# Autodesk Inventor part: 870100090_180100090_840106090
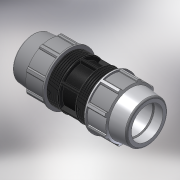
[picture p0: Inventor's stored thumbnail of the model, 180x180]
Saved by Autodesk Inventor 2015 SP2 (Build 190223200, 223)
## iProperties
Created: 2017-02
Part Number: 870100090_180100090_840106090
Material: Generic
Description: PLASSON COUPLER 90-90
Document SubType Name: Modeling
Designer: KIM
Mass: 3885.53 g
Surface Area: 4713.66 cm^2
Volume: 3885.53 cm^3
Density: 1 g/cm^3
Appearance: Default
Author: KIM
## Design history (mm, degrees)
derived "87010.ipt"
feature "Solid1::87010.ipt"
tag "TaggingFeature1"
body "Solid1"
other parameters: "d1" = 334, "d4" = 27.83333, "d5" = 47.71429, "d7" = 152, "d8" = 114, "d9" = 47.71429, "d11" = 4.77143, "d12" = 121.6, "d13" = 120 deg, "d14" = 117, "d15" = 6 deg, "d16" = 136.8, "d18" = 4.5, "d19" = 35 deg, "d20" = 17.5 deg, "d21" = 141.36, "d23" = 0, "d25" = 360 deg, "d27" = 3.04, "d33" = 1.8, "d34" = 7.6, "d36" = 0, "d37" = 1.8, "d38" = 1.8, "d40" = 360 deg, "d42" = 60.12, "d46" = 2.7, "d50" = 4.175, "d51" = 0, "d53" = 3.05371, "d54" = 3.05371, "d57" = 6.10743, "d62" = 134.064, "d64" = 81, "d65" = 164, "E_" = 152, "H_" = 334, "l_" = 164, "d52" = 30.53714
